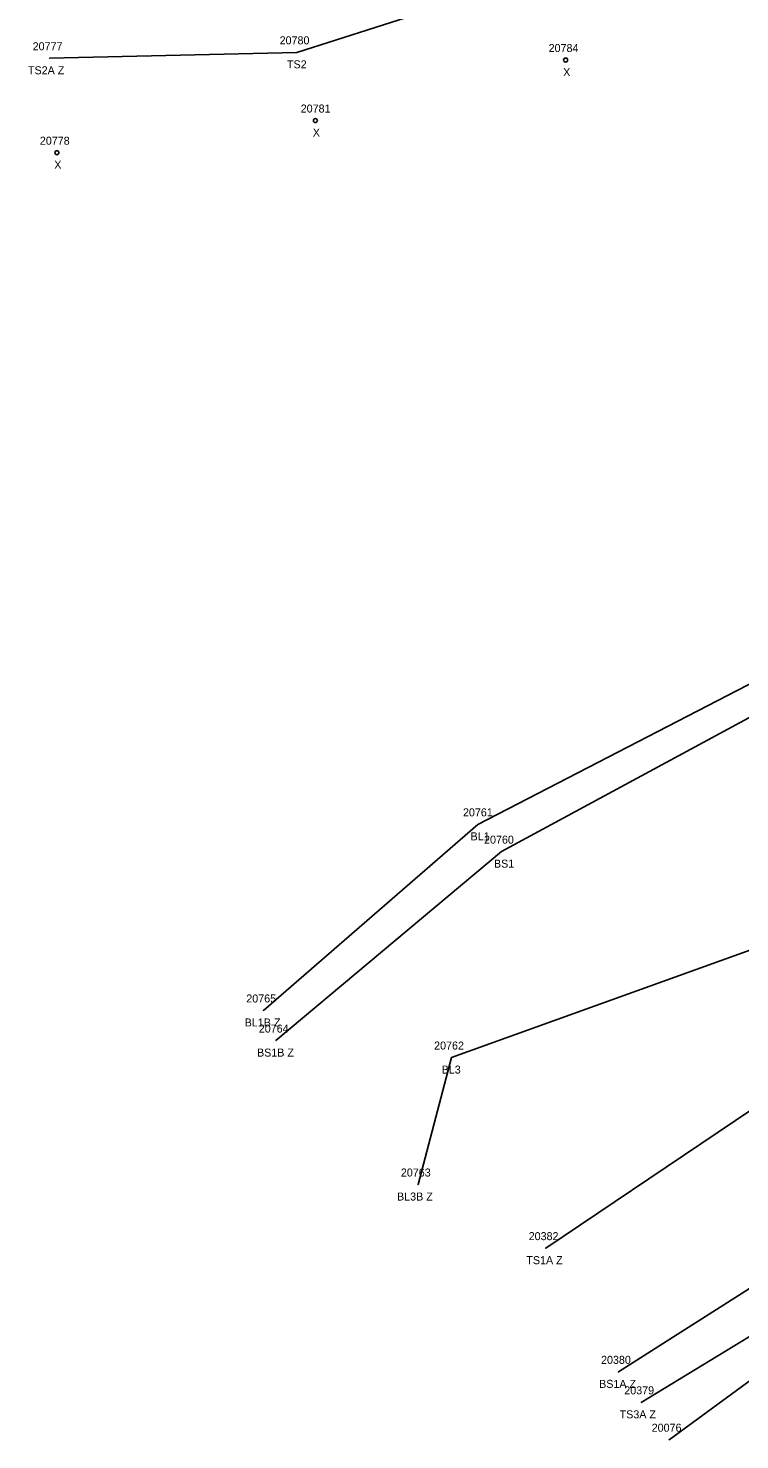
# Model space of a CAD drawing. Extents: x 1813127 to 1814107, y 1178171 to 1179078.
# Drawn here: x 1813497.3 to 1813586.1, y 1178474.3 to 1178650.6 of the extents above; entities that cross this region are included whole.
import ezdxf

# ---------------------------------------------------------------- set-up
doc = ezdxf.new("R2010")
doc.units = 0
for name, color, linetype in [('RD_DTM_BkLn1', 7, 'Continuous'), ('RD_DTM_BkLn2', 7, 'Continuous'), ('RD_EX_Road', 7, 'Continuous'), ('RD_EX_Road_txCode', 7, 'Continuous'), ('RD_SMD_Locator', 7, 'Continuous'), ('RD_SMD_Misc', 7, 'Continuous')]:
    doc.layers.add(name, color=color, linetype=linetype)

msp = doc.modelspace()

# ---------------------------------------------------------------- linework, layer by layer
at = {"layer": 'RD_DTM_BkLn1'}
for points in [[(1813684.91, 1178649.24), (1813672.9, 1178626.57), (1813636.59, 1178600.97), (1813597.02, 1178573.71), (1813553.38, 1178551.14), (1813526.62, 1178527.89)], [(1813683.38, 1178591.62), (1813653.58, 1178575.69), (1813601.65, 1178540.57), (1813550.07, 1178522.01), (1813545.91, 1178506.15)]]:
    msp.add_lwpolyline(points, dxfattribs=at)
at = {"layer": 'RD_DTM_BkLn2'}
for p, q in [((1813570.91, 1178482.75), (1813612.94, 1178509.5)), ((1813573.76, 1178478.94), (1813617.33, 1178505.47))]:
    msp.add_line(p, q, dxfattribs=at)
for points in [[(1813499.93, 1178646.84), (1813530.8, 1178647.58), (1813558.17, 1178656.33), (1813572.78, 1178667.8)], [(1813687.73, 1178647.6), (1813673.94, 1178621.63), (1813639.04, 1178598.07), (1813598.95, 1178570.83), (1813556.33, 1178547.73), (1813528.18, 1178524.13)], [(1813561.84, 1178498.2), (1813604.88, 1178527.17), (1813645.67, 1178546.08), (1813692.97, 1178578.89), (1813742.95, 1178609.65)]]:
    msp.add_lwpolyline(points, dxfattribs=at)
at = {"layer": 'RD_EX_Road'}
msp.add_lwpolyline([(1813577.25, 1178474.27), (1813618.17, 1178504.26), (1813659.38, 1178535.26), (1813701.1, 1178565.69), (1813742.11, 1178594.54), (1813782.72, 1178623.8), (1813791.22, 1178630.12), (1813798.98, 1178638.62), (1813801.09, 1178645.46), (1813800.26, 1178651.57), (1813775.58, 1178673.13), (1813768.46, 1178675.91), (1813762.33, 1178681.89)], dxfattribs=at)
at = {"layer": 'RD_SMD_Locator'}
for centre, radius in [((1813499.93, 1178646.84), 0.001), ((1813530.8, 1178647.58), 0.001), ((1813564.33, 1178646.62), 0.25), ((1813533.1, 1178639.06), 0.25), ((1813500.84, 1178635.04), 0.25), ((1813553.38, 1178551.14), 0.001), ((1813556.33, 1178547.73), 0.001), ((1813526.62, 1178527.89), 0.001), ((1813528.18, 1178524.13), 0.001), ((1813550.07, 1178522.01), 0.001), ((1813545.91, 1178506.15), 0.001), ((1813561.84, 1178498.2), 0.001), ((1813570.91, 1178482.75), 0.001), ((1813573.76, 1178478.94), 0.001), ((1813577.25, 1178474.27), 0.001)]:
    msp.add_circle(centre, radius, dxfattribs=at)

# ---------------------------------------------------------------- texts
at = {"layer": 'RD_EX_Road_txCode'}
msp.add_text('20076', height=1, dxfattribs=at).set_placement((1813575.07, 1178475.27))
at = {"layer": 'RD_SMD_Misc'}
for s, p in [('20780', (1813528.64, 1178648.58)), ('20777', (1813497.82, 1178647.84)), ('20784', (1813562.21, 1178647.62)), ('TS2', (1813529.56, 1178645.58)), ('TS2A Z', (1813497.24, 1178644.84)), ('X', (1813564.02, 1178644.62)), ('20781', (1813531.27, 1178640.06)), ('X', (1813532.78, 1178637.06)), ('20778', (1813498.72, 1178636.04)), ('X', (1813500.52, 1178633.04)), ('20761', (1813551.52, 1178552.14)), ('BL1', (1813552.46, 1178549.14)), ('20760', (1813554.15, 1178548.73)), ('BS1', (1813555.39, 1178545.73)), ('20765', (1813524.48, 1178528.89)), ('BL1B Z', (1813524.28, 1178525.89)), ('20764', (1813526.04, 1178525.13)), ('BS1B Z', (1813525.82, 1178522.13)), ('20762', (1813547.92, 1178523.01)), ('BL3', (1813548.86, 1178520.01)), ('20763', (1813543.77, 1178507.15)), ('BL3B Z', (1813543.29, 1178504.15)), ('20382', (1813559.72, 1178499.2)), ('TS1A Z', (1813559.43, 1178496.2)), ('20380', (1813568.75, 1178483.75)), ('BS1A Z', (1813568.51, 1178480.75)), ('20379', (1813571.65, 1178479.94)), ('TS3A Z', (1813571.07, 1178476.94))]:
    msp.add_text(s, height=1, dxfattribs=at).set_placement(p)

doc.saveas('drawing.dxf')
